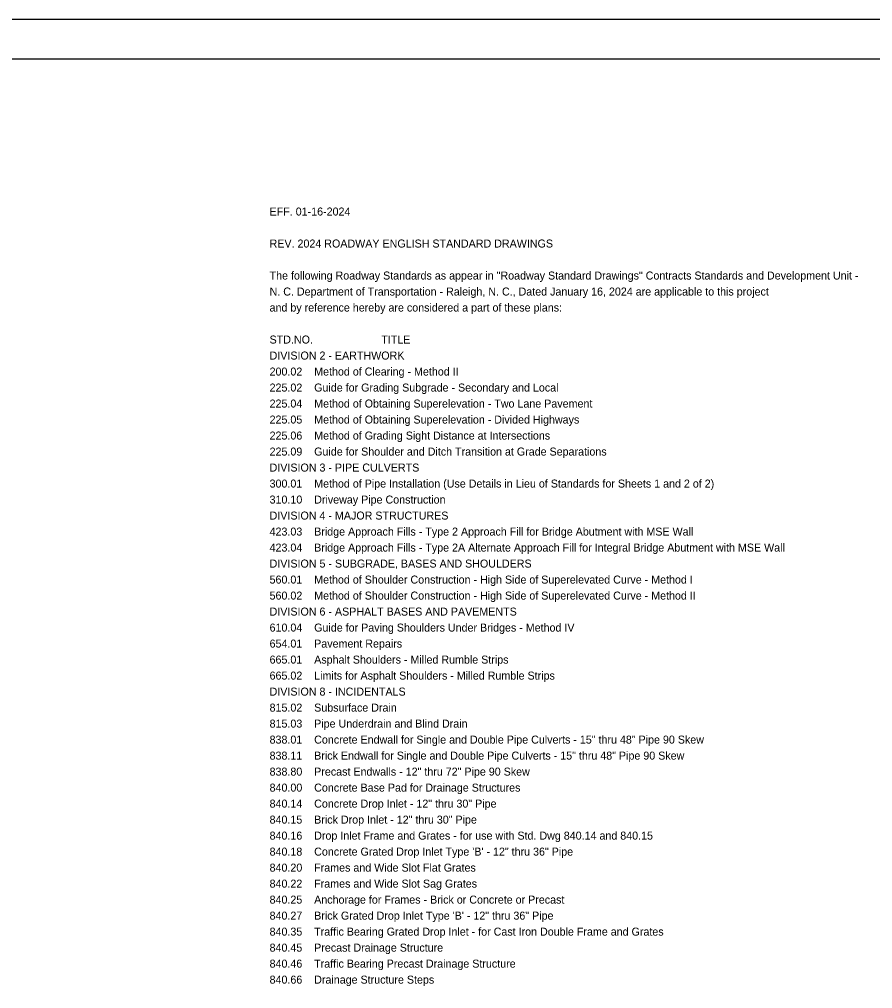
# Model space of a CAD drawing. Extents: x 1844369 to 1844800, y 671424 to 671721.
# Drawn here: x 1844512.37 to 1844552.92, y 671547.07 to 671593.11 of the extents above; entities that cross this region are included whole.
import ezdxf

# ---------------------------------------------------------------- set-up
doc = ezdxf.new("R2010")
doc.units = 0
for name, color, linetype in [('Sheet Data Text CELL', 7, 'Continuous'), ('Sheet_Clip_Boundary_CELL', 7, 'Continuous'), ('Sheet_Plan_CELL', 7, 'Continuous')]:
    doc.layers.add(name, color=color, linetype=linetype)

msp = doc.modelspace()

# ---------------------------------------------------------------- linework, layer by layer
at = {"layer": 'Sheet_Clip_Boundary_CELL'}
msp.add_lwpolyline([(1844581.788, 671593.106), (1844440.123, 671593.106), (1844440.123, 671501.068), (1844581.788, 671501.068)], close=True, dxfattribs=at)
at = {"layer": 'Sheet_Plan_CELL'}
msp.add_line((1844579.905, 671591.223), (1844443.146, 671591.223), dxfattribs=at)

# ---------------------------------------------------------------- texts
at = {"layer": 'Sheet Data Text CELL'}
for s, p in [('EFF. 01-16-2024', (1844524.261, 671583.79)), ('REV. 2024 ROADWAY ENGLISH STANDARD DRAWINGS', (1844524.261, 671582.27)), ('The following Roadway Standards as appear in "Roadway Standard Drawings" Contracts Standards and Development Unit -', (1844524.261, 671580.75)), ('N. C. Department of Transportation - Raleigh, N. C., Dated January 16, 2024 are applicable to this project', (1844524.261, 671579.99)), ('and by reference hereby are considered a part of these plans:', (1844524.261, 671579.23)), ('STD.NO.                       TITLE', (1844524.261, 671577.71)), ('DIVISION 2 - EARTHWORK', (1844524.261, 671576.95)), ('200.02    Method of Clearing - Method II', (1844524.261, 671576.19)), ('225.02    Guide for Grading Subgrade - Secondary and Local', (1844524.261, 671575.43)), ('225.04    Method of Obtaining Superelevation - Two Lane Pavement', (1844524.261, 671574.67)), ('225.05    Method of Obtaining Superelevation - Divided Highways', (1844524.261, 671573.91)), ('225.06    Method of Grading Sight Distance at Intersections', (1844524.261, 671573.15)), ('225.09    Guide for Shoulder and Ditch Transition at Grade Separations', (1844524.261, 671572.39)), ('DIVISION 3 - PIPE CULVERTS', (1844524.261, 671571.63)), ('300.01    Method of Pipe Installation (Use Details in Lieu of Standards for Sheets 1 and 2 of 2)', (1844524.261, 671570.87)), ('310.10    Driveway Pipe Construction', (1844524.261, 671570.11)), ('DIVISION 4 - MAJOR STRUCTURES', (1844524.261, 671569.35)), ('423.03    Bridge Approach Fills - Type 2 Approach Fill for Bridge Abutment with MSE Wall', (1844524.261, 671568.59)), ('423.04    Bridge Approach Fills - Type 2A Alternate Approach Fill for Integral Bridge Abutment with MSE Wall', (1844524.261, 671567.83)), ('DIVISION 5 - SUBGRADE, BASES AND SHOULDERS', (1844524.261, 671567.07)), ('560.01    Method of Shoulder Construction - High Side of Superelevated Curve - Method I', (1844524.261, 671566.31)), ('560.02    Method of Shoulder Construction - High Side of Superelevated Curve - Method II', (1844524.261, 671565.55)), ('DIVISION 6 - ASPHALT BASES AND PAVEMENTS', (1844524.261, 671564.79)), ('610.04    Guide for Paving Shoulders Under Bridges - Method IV', (1844524.261, 671564.03)), ('654.01    Pavement Repairs', (1844524.261, 671563.27)), ('665.01    Asphalt Shoulders - Milled Rumble Strips', (1844524.261, 671562.51)), ('665.02    Limits for Asphalt Shoulders - Milled Rumble Strips', (1844524.261, 671561.75)), ('DIVISION 8 - INCIDENTALS', (1844524.261, 671560.99)), ('815.02    Subsurface Drain', (1844524.261, 671560.23)), ('815.03    Pipe Underdrain and Blind Drain', (1844524.261, 671559.47)), ('838.01    Concrete Endwall for Single and Double Pipe Culverts - 15" thru 48" Pipe 90 Skew', (1844524.261, 671558.71)), ('838.11    Brick Endwall for Single and Double Pipe Culverts - 15" thru 48" Pipe 90 Skew', (1844524.261, 671557.95)), ('838.80    Precast Endwalls - 12" thru 72" Pipe 90 Skew', (1844524.261, 671557.19)), ('840.00    Concrete Base Pad for Drainage Structures', (1844524.261, 671556.43)), ('840.14    Concrete Drop Inlet - 12" thru 30" Pipe', (1844524.261, 671555.67)), ('840.15    Brick Drop Inlet - 12" thru 30" Pipe', (1844524.261, 671554.91)), ('840.16    Drop Inlet Frame and Grates - for use with Std. Dwg 840.14 and 840.15', (1844524.261, 671554.15)), ('840.18    Concrete Grated Drop Inlet Type \'B\' - 12" thru 36" Pipe', (1844524.261, 671553.39)), ('840.20    Frames and Wide Slot Flat Grates', (1844524.261, 671552.63)), ('840.22    Frames and Wide Slot Sag Grates', (1844524.261, 671551.87)), ('840.25    Anchorage for Frames - Brick or Concrete or Precast', (1844524.261, 671551.11)), ('840.27    Brick Grated Drop Inlet Type \'B\' - 12" thru 36" Pipe', (1844524.261, 671550.35)), ('840.35    Traffic Bearing Grated Drop Inlet - for Cast Iron Double Frame and Grates', (1844524.261, 671549.59)), ('840.45    Precast Drainage Structure', (1844524.261, 671548.83)), ('840.46    Traffic Bearing Precast Drainage Structure', (1844524.261, 671548.07)), ('840.66    Drainage Structure Steps', (1844524.261, 671547.31))]:
    msp.add_text(s, height=0.38, dxfattribs=at).set_placement(p)

doc.saveas('drawing.dxf')
